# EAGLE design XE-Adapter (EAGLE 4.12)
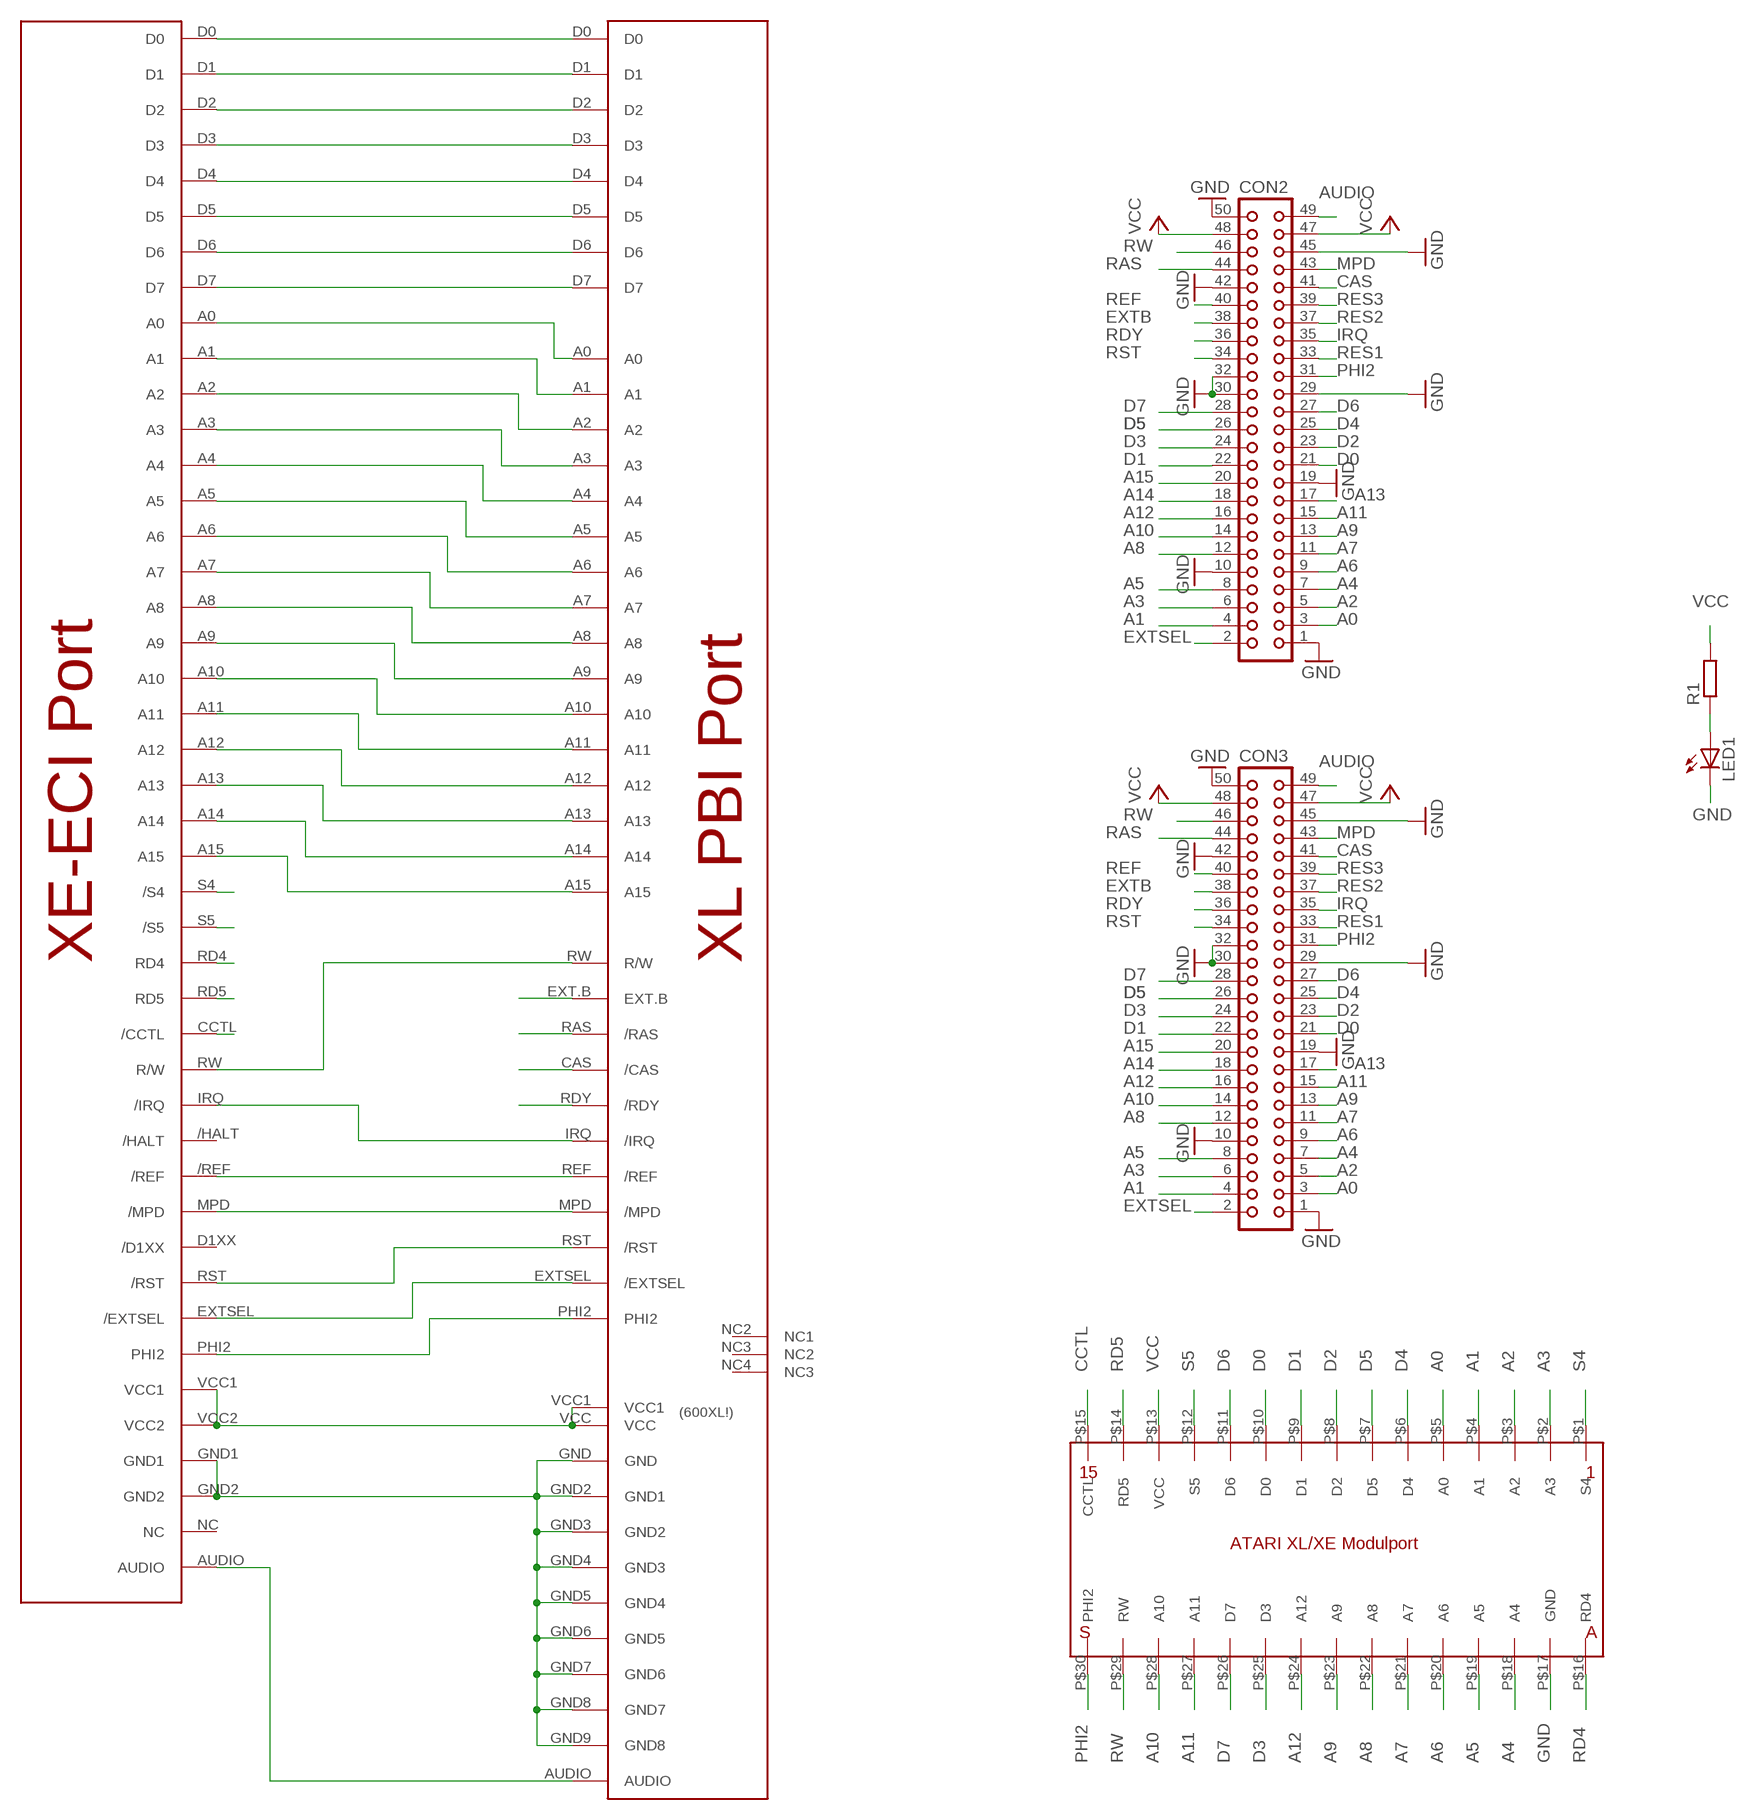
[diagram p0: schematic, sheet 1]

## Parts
CON2  CON50  [CON50]
CON3  CON50  [CON50]
LED1  LEDCHIPLED_1206  [CHIPLED_1206]
R1  R-EU_M0805  [M0805]
U$1  XE-ECI  [XE-ECI]
U$2  XL-PBI  [XL-PBI]
U$3  ATARI_MODULPORT  [MODUL_PORT]

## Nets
A0: CON2.3 CON3.3 U$1.A0 U$2.A0 U$3.P$5(A0)
A1: CON2.4 CON3.4 U$1.A1 U$2.A1 U$3.P$4(A1)
A2: CON2.5 CON3.5 U$1.A2 U$2.A2 U$3.P$3(A2)
A3: CON2.6 CON3.6 U$1.A3 U$2.A3 U$3.P$2(A3)
A4: CON2.7 CON3.7 U$1.A4 U$2.A4 U$3.P$18(A4)
A5: CON2.8 CON3.8 U$1.A5 U$2.A5 U$3.P$19(A5)
A6: CON2.9 CON3.9 U$1.A6 U$2.A6 U$3.P$20(A6)
A7: CON2.11 CON3.11 U$1.A7 U$2.A7 U$3.P$21(A7)
A8: CON2.12 CON3.12 U$1.A8 U$2.A8 U$3.P$22(A8)
A9: CON2.13 CON3.13 U$1.A9 U$2.A9 U$3.P$23(A9)
A10: CON2.14 CON3.14 U$1.A10 U$2.A10 U$3.P$28(A10)
A11: CON2.15 CON3.15 U$1.A11 U$2.A11 U$3.P$27(A11)
A12: CON2.16 CON3.16 U$1.A12 U$2.A12 U$3.P$24(A12)
A13: CON2.17 CON3.17 U$1.A13 U$2.A13
A14: CON2.18 CON3.18 U$1.A14 U$2.A14
A15: CON2.20 CON3.20 U$1.A15 U$2.A15
AUDIO: CON2.49 CON3.49 U$1.AUDIO U$2.AUDIO
CAS: CON2.41 CON3.41 U$2.CAS(/CAS)
CCTL: U$1.CCTL(/CCTL) U$3.P$15(CCTL)
D0: CON2.21 CON3.21 U$1.D0 U$2.D0 U$3.P$10(D0)
D1: CON2.22 CON3.22 U$1.D1 U$2.D1 U$3.P$9(D1)
D2: CON2.23 CON3.23 U$1.D2 U$2.D2 U$3.P$8(D2)
D3: CON2.24 CON3.24 U$1.D3 U$2.D3 U$3.P$25(D3)
D4: CON2.25 CON3.25 U$1.D4 U$2.D4 U$3.P$6(D4)
D5: CON2.26 CON3.26 U$1.D5 U$2.D5 U$3.P$7(D5)
D6: CON2.27 CON3.27 U$1.D6 U$2.D6 U$3.P$11(D6)
D7: CON2.28 CON3.28 U$1.D7 U$2.D7 U$3.P$26(D7)
EXTB: CON2.38 CON3.38 U$2.EXT.B
EXTSEL: CON2.2 CON3.2 U$1.EXTSEL(/EXTSEL) U$2.EXTSEL(/EXTSEL)
GND: CON2.1 CON2.10 CON2.19 CON2.29 CON2.30 CON2.32 CON2.42 CON2.45 CON2.50 CON3.1 CON3.10 CON3.19 CON3.29 CON3.30 CON3.32 CON3.42 CON3.45 CON3.50 LED1.C U$1.GND1 U$1.GND2 U$2.GND U$2.GND2(GND1) U$2.GND3(GND2) U$2.GND4(GND3) U$2.GND5(GND4) U$2.GND6(GND5) U$2.GND7(GND6) U$2.GND8(GND7) U$2.GND9(GND8) U$3.P$17(GND)
IRQ: CON2.35 CON3.35 U$1.IRQ(/IRQ) U$2.IRQ(/IRQ)
MPD: CON2.43 CON3.43 U$1.MPD(/MPD) U$2.MPD(/MPD)
N$4: LED1.A R1.1
PHI2: CON2.31 CON3.31 U$1.PHI2 U$2.PHI2 U$3.P$30(PHI2)
RAS: CON2.44 CON3.44 U$2.RAS(/RAS)
RD4: U$1.RD4 U$3.P$16(RD4)
RD5: U$1.RD5 U$3.P$14(RD5)
RDY: CON2.36 CON3.36 U$2.RDY(/RDY)
REF: CON2.40 CON3.40 U$1./REF U$2.REF(/REF)
RES1: CON2.33 CON3.33
RES2: CON2.37 CON3.37
RES3: CON2.39 CON3.39
RST: CON2.34 CON3.34 U$1.RST(/RST) U$2.RST(/RST)
RW: CON2.46 CON3.46 U$1.RW(R/W) U$2.RW(R/W) U$3.P$29(RW)
S4: U$1.S4(/S4) U$3.P$1(S4)
S5: U$1.S5(/S5) U$3.P$12(S5)
VCC: CON2.47 CON2.48 CON3.47 CON3.48 R1.2 U$1.VCC1 U$1.VCC2 U$2.VCC U$2.VCC1 U$3.P$13(VCC)
Unconnected: U$1./HALT U$1.D1XX(/D1XX) U$1.NC U$2.NC2(NC1) U$2.NC3(NC2) U$2.NC4(NC3)

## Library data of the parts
CON2 CON3 = con-harting:CON50: CONNECTOR
LED1 = led:LED: LED
R1 = rcl:R-EU_: RESISTOR, European symbol
U$1 = wf-atari:XE-ECI
U$2 = wf-atari:XL-PBI
U$3 = wf-atari:ATARI_MODULPORT

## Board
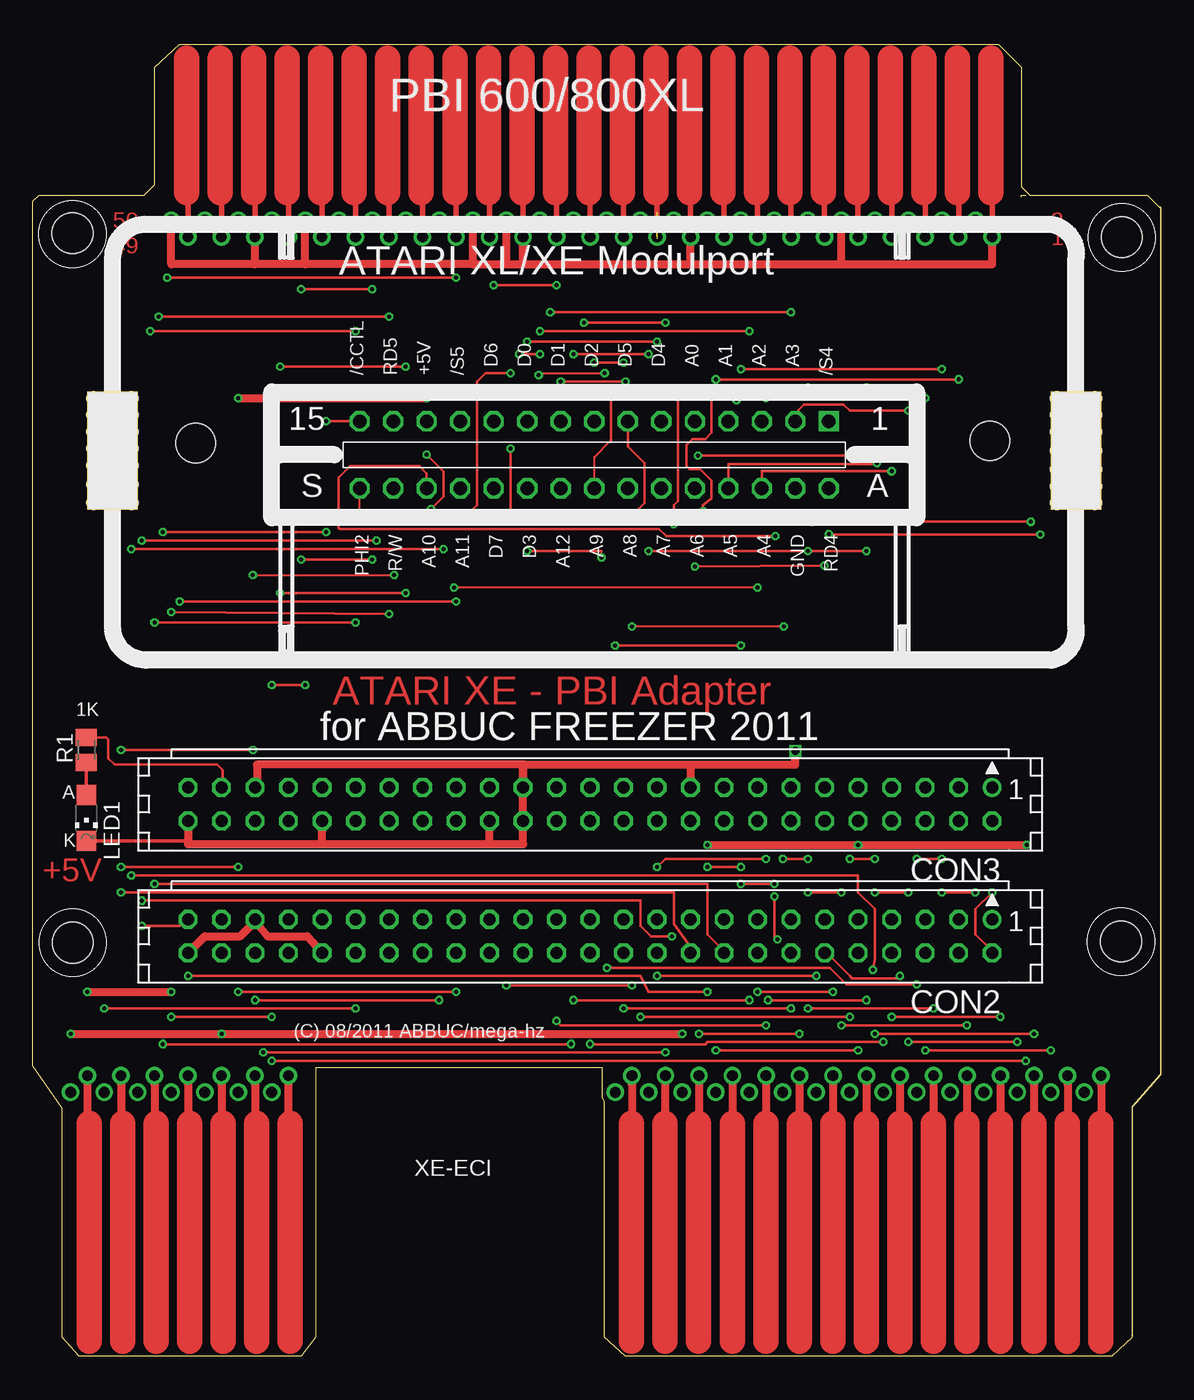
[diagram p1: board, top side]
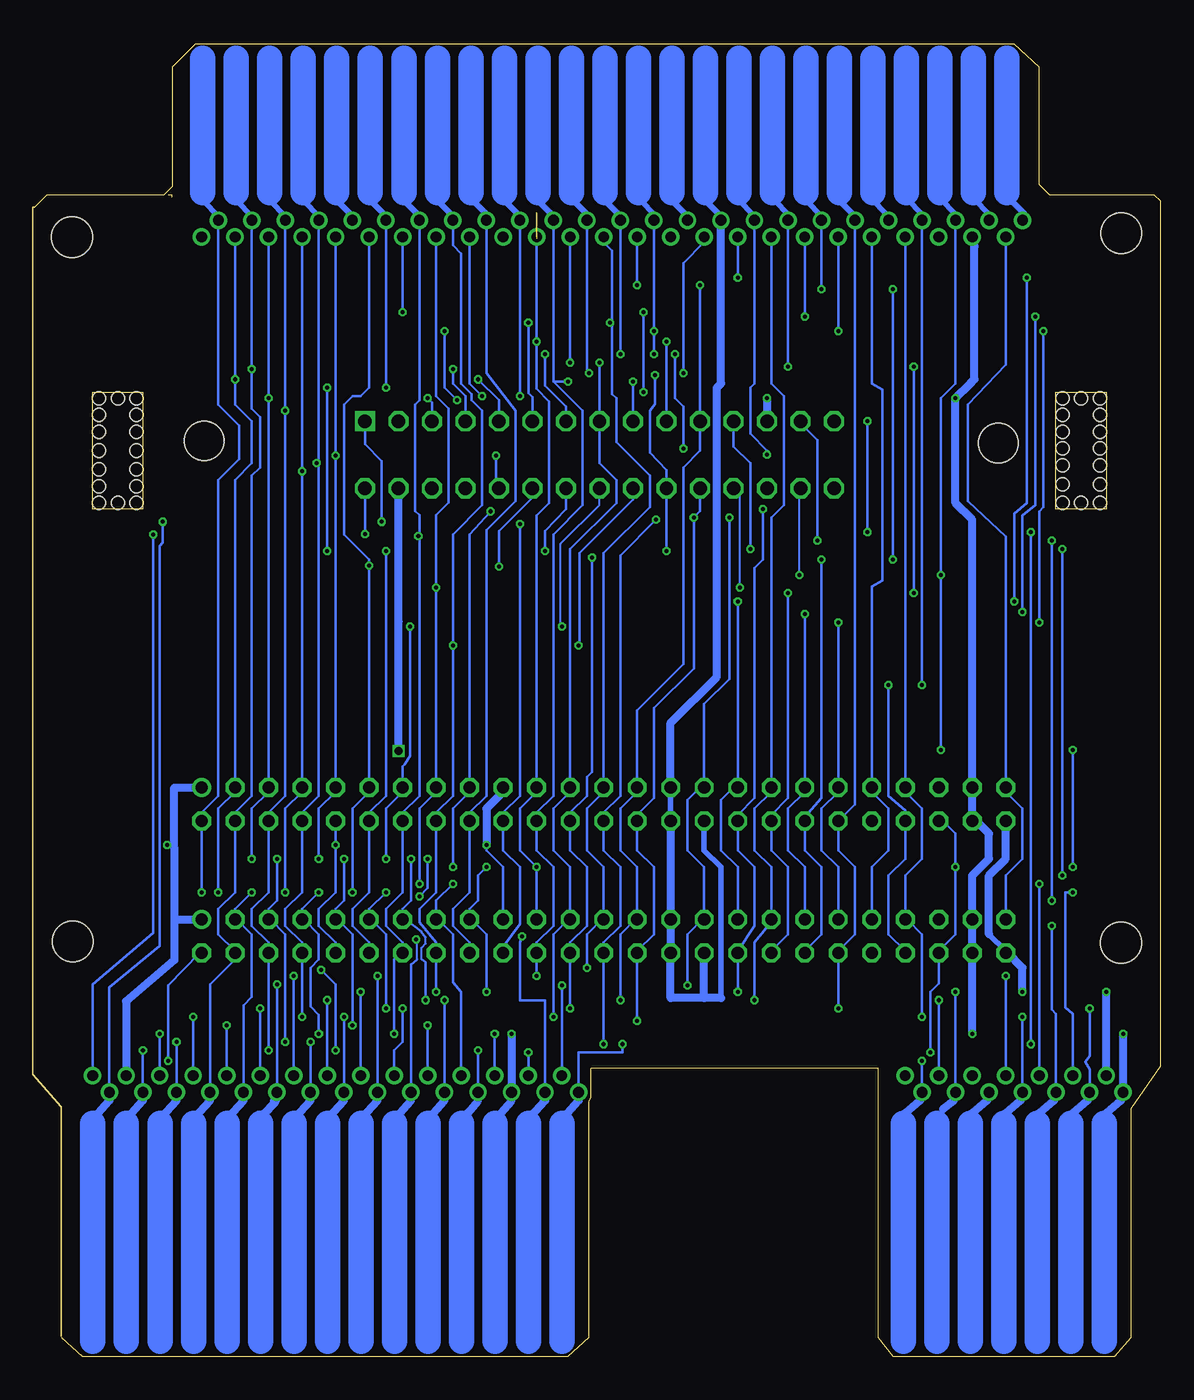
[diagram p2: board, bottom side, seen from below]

Size 85.49 x 99.44 mm. Coordinates in mm from the lower left corner, seen from the top.
Outline: 85.41,87.06 84.45,88.01 75.56,88.01 74.93,88.64 74.93,97.69 73.18,99.44 12.22,99.44 12.06,99.44 11.11,99.44 9.21,97.69 9.21,88.8 8.41,88.01 0.48,88.01 0,87.53 0,22 2.22,18.78 2.22,1.43 3.49,0 20.32,0 21.43,1.43 21.43,21.84 43.18,21.84
Outline: 83.34,1.43 81.76,0 44.93,0 43.34,1.43 43.34,19.29 43.18,19.61 43.18,21.83
Outline: 83.34,1.51 83.34,18.89 85.49,21.35 85.49,87.07 85.41,87.07
Copper layers (1*16): Top 0.035mm / dielectric 1.5mm / Bottom 0.035mm
Design rules "ITead_rule": minimum track width 6mil, minimum drill 12mil, track to track 6mil, track to pad 6mil, pad to pad 6mil, via to via 6mil, smd to smd 0mil, copper to edge 10mil, drill to drill 10mil, minimum pad ring 10mil, minimum via ring 6mil, stop-mask expansion 2mil, vias tented up to drill 100mil, thermal gap 10mil
Holes 1 mm at 4.6,72.61 6.03,72.61 7.46,72.61 4.6,71.34 4.6,70.07 4.6,68.8 4.6,67.53 4.6,66.1 4.6,64.67 7.46,64.67 6.03,64.67 7.46,66.1 7.46,67.53 7.46,68.8 7.46,71.34 7.46,70.07 77.63,72.61 80.49,72.61 77.63,64.67 80.49,64.67 79.06,64.67 79.06,72.61 77.63,71.34 77.63,70.07 77.63,65.94 77.63,67.21 77.63,68.64 80.49,68.64 80.49,70.07 80.49,71.34 80.49,67.21 80.49,65.94
Holes 3.1 mm at 2.98,85.13 82.53,84.81 3.02,31.35 82.47,31.43

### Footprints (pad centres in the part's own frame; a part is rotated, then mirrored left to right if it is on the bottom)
CON50 = drill 0.914 round: 1 -30.48,-1.27 | drill 0.914 octagon: 2 -30.48,1.27; 3 -27.94,-1.27; 4 -27.94,1.27; 5 -25.4,-1.27; 6 -25.4,1.27; 7 -22.86,-1.27; 8 -22.86,1.27; 9 -20.32,-1.27; 10 -20.32,1.27; 11 -17.78,-1.27; 12 -17.78,1.27; 13 -15.24,-1.27; 14 -15.24,1.27; 15 -12.7,-1.27; 16 -12.7,1.27; 17 -10.16,-1.27; 18 -10.16,1.27; 19 -7.62,-1.27; 20 -7.62,1.27; 21 -5.08,-1.27; 22 -5.08,1.27; 23 -2.54,-1.27; 24 -2.54,1.27; 25 0,-1.27; 26 0,1.27; 27 2.54,-1.27; 28 2.54,1.27; 29 5.08,-1.27; 30 5.08,1.27; 31 7.62,-1.27; 32 7.62,1.27; 33 10.16,-1.27; 34 10.16,1.27; 35 12.7,-1.27; 36 12.7,1.27; 37 15.24,-1.27; 38 15.24,1.27; 39 17.78,-1.27; 40 17.78,1.27; 41 20.32,-1.27; 42 20.32,1.27; 43 22.86,-1.27; 44 22.86,1.27; 45 25.4,-1.27; 46 25.4,1.27; 47 27.94,-1.27; 48 27.94,1.27; 49 30.48,-1.27; 50 30.48,1.27
CHIPLED_1206 = smd 1.5 x 1.5: A 0,-1.75; C 0,1.75
M0805 = smd 1.3 x 1.6: 1 -0.95,0; 2 0.95,0
XE-ECI = drill 0.813 round: /HALT -17.78,8.89; /REF -26.67,7.62; A0 37.465,7.62; A1 40.005,7.62; A2 42.545,7.62; A3 45.085,7.62; A4 43.815,8.89; A5 41.275,8.89; A6 38.735,8.89; A7 36.195,8.89; A8 33.655,8.89; A9 31.115,8.89; A10 18.415,8.89; A11 20.955,8.89; A12 28.575,8.89; A13 -20.32,8.89; A14 -22.86,8.89; A15 -25.4,8.89; AUDIO -24.13,7.62; CCTL 12.065,7.62; D0 24.765,7.62; D1 27.305,7.62; D1XX -19.05,7.62; D2 29.845,7.62; D3 26.035,8.89; D4 34.925,7.62; D5 32.385,7.62; D6 22.225,7.62; D7 23.495,8.89; EXTSEL -13.97,7.62; GND1 -27.94,8.89; GND2 46.355,8.89; IRQ -15.24,8.89; MPD -21.59,7.62; NC -12.7,8.89; PHI2 13.335,8.89; RD4 48.895,8.89; RD5 14.605,7.62; RST -16.51,7.62; RW 15.875,8.89; S4 47.625,7.62; S5 19.685,7.62; VCC1 -29.21,7.62; VCC2 17.145,7.62
XL-PBI = drill 0.813 round: A0 31.115,-8.255; A1 29.845,-6.985; A2 28.575,-8.255; A3 27.305,-6.985; A4 26.035,-8.255; A5 24.765,-6.985; A6 23.495,-8.255; A7 20.955,-8.255; A8 19.685,-6.985; A9 18.415,-8.255; A10 17.145,-6.985; A11 15.875,-8.255; A12 14.605,-6.985; A13 13.335,-8.255; A14 12.065,-6.985; A15 9.525,-6.985; AUDIO -27.305,-8.255; CAS -17.145,-8.255; D0 8.255,-8.255; D1 6.985,-6.985; D2 5.715,-8.255; D3 4.445,-6.985; D4 3.175,-8.255; D5 1.905,-6.985; D6 0.635,-8.255; D7 -0.635,-6.985; EXT.B -13.335,-6.985; EXTSEL 32.385,-6.985; GND -28.575,-6.985; GND2 -18.415,-6.985; GND3 -5.715,-6.985; GND4 -3.175,-6.985; GND5 22.225,-6.985; GND6 33.655,-8.255; GND7 10.795,-8.255; GND8 -1.905,-8.255; GND9 -22.225,-8.255; IRQ -9.525,-8.255; MPD -19.685,-8.255; NC2 -6.985,-8.255; NC3 -12.065,-8.255; NC4 -14.605,-8.255; PHI2 -4.445,-8.255; RAS -20.955,-6.985; RDY -10.795,-6.985; REF -15.875,-6.985; RST -8.255,-6.985; RW -23.495,-6.985; VCC -24.765,-8.255; VCC1 -26.035,-6.985
MODUL_PORT = drill 1.016 square: P$1 18.098,1.587 | drill 1.016 octagon: P$2 15.557,1.587; P$3 13.018,1.587; P$4 10.477,1.587; P$5 7.938,1.587; P$6 5.397,1.587; P$7 2.857,1.587; P$8 0.318,1.587; P$9 -2.223,1.587; P$10 -4.763,1.587; P$11 -7.303,1.587; P$12 -9.842,1.587; P$13 -12.383,1.587; P$14 -14.922,1.587; P$15 -17.462,1.587; P$16 18.098,-3.493; P$17 15.557,-3.493; P$18 13.018,-3.493; P$19 10.477,-3.493; P$20 7.938,-3.493; P$21 5.397,-3.493; P$22 2.857,-3.493; P$23 0.318,-3.493; P$24 -2.223,-3.493; P$25 -4.763,-3.493; P$26 -7.303,-3.493; P$27 -9.842,-3.493; P$28 -12.383,-3.493; P$29 -14.922,-3.493; P$30 -17.462,-3.493 | hole 3: 30.294,0.102; -29.9,-0.057

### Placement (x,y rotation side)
CON2  42.23,31.83 180 top
CON3  42.23,41.83 180 top
LED1  4.05,40.8 180 top
R1  4.05,45.96 90 top
U$1  32.07,12.38 0 top
U$2  39.05,93.09 0 top
U$3  42.23,69.28 0 top

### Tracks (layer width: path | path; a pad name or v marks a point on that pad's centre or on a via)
A0  (via drill 0.3)
  Top 0.203: v68.9,35.16 v71.44,35.16 | v70.17,74.04 v51.75,74.04
  Bottom 0.203: U$1.A0 69.53,26.59 68.9,27.23 68.9,31.99 70.17,33.26 | 70.17,33.26 CON2.3 | 70.17,33.26 70.17,33.89 v68.9,35.16 | v71.44,35.16 71.44,41.51 70.17,42.78 CON3.3 70.17,66.42 68.9,67.69 68.9,70.86 70.17,72.14 v70.17,74.04 | v70.17,74.04 70.17,73.72 | U$3.P$5 50.16,72.45 v51.75,74.04 | v70.17,74.04 | 70.12,84.81 70.17,84.85 U$2.A0 v70.17,74.04
A1  (via drill 0.3)
  Top 0.203: v68.9,74.83 v53.66,74.83
  Bottom 0.203: U$1.A1 72.07,28.18 70.17,30.08 CON2.4 70.17,30.72 71.44,31.99 71.44,33.89 70.17,35.16 CON3.4 70.17,41.2 68.9,42.47 68.9,66.74 68.26,67.37 68.26,71.18 68.9,71.82 v68.9,74.83 68.9,85.49 | U$3.P$4 52.7,72.77 53.66,73.72 v53.66,74.83 | 68.9,86.12 U$2.A1 68.9,85.49 | 68.9,85.49 68.9,85.41
A2  (via drill 0.3)
  Top 0.203: v66.36,23.81 v74.61,23.81 | v66.99,37.7 v68.9,37.7 | v67.63,72.61 v55.56,72.61
  Bottom 0.203: v66.36,23.81 66.36,31.99 67.47,33.1 CON2.5 67.63,33.89 66.99,34.53 v66.99,37.7 | v74.61,23.81 U$1.A2 | v68.9,37.7 68.9,41.51 67.63,42.78 CON3.5 v67.63,72.61 67.63,84.93 | U$3.P$3 55.24,72.29 v55.56,72.61 | 67.63,84.93 67.62,85.17 | 67.63,84.93 U$2.A2
A3  (via drill 0.3)
  Top 0.203: v67.63,23.18 v77.15,23.18 | v66.36,71.66 61.91,71.66 61.44,72.14 58.42,72.14 57.78,71.5 U$3.P$2
  Bottom 0.203: v77.15,23.18 U$1.A3 | v67.63,23.18 CON2.6 67.63,31.35 68.9,32.62 68.9,33.89 67.63,35.16 CON3.6 67.63,41.2 66.36,42.47 66.36,72.14 | 66.36,72.14 v66.36,71.66 | 66.36,85.49 66.36,85.41 | 66.36,85.49 U$2.A3 | 66.36,72.14 66.36,85.49
A4  (via drill 0.3)
  Top 0.203: v63.82,24.45 v75.88,24.45 | v63.82,35.16 v66.36,35.16 | U$3.P$18 55.24,67.07 v65.09,67.07
  Bottom 0.203: v75.88,24.45 U$1.A4 | v63.82,35.16 65.09,33.89 CON2.7 64.93,33.1 63.82,31.99 63.82,30.08 64.45,29.45 64.45,26.51 63.82,25.88 v63.82,24.45 | v66.36,35.16 66.36,41.51 65.09,42.78 CON3.7 65.4,43.42 65.09,43.73 v65.09,67.07 65.09,84.77 | 65.09,84.77 65.09,84.69 65.04,84.65 | 65.09,84.77 U$2.A4
A5  (via drill 0.3)
  Top 0.203: v65.09,25.72 v73.34,25.72 | U$3.P$19 52.7,67.63 64.06,67.63 v63.98,67.71
  Bottom 0.203: v73.34,25.72 U$1.A5 | v65.09,25.72 CON2.8 65.09,31.35 66.36,32.62 66.36,33.89 65.09,35.16 CON3.8 | CON3.8 65.09,40.88 | CON3.8 65.09,41.2 63.82,42.47 63.82,67.63 | 63.82,86.12 U$2.A5 63.82,85.57 | 63.82,85.57 63.82,85.41 | v63.98,67.71 63.9,67.71 63.82,67.63 | 63.82,67.63 63.82,85.57
A6  (via drill 0.3)
  Top 0.203: v61.28,25.08 v70.8,25.08 | v61.91,37.7 v63.82,37.7 | v62.55,68.26 v50.4,68.26
  Bottom 0.203: v70.8,25.08 U$1.A6 | v61.28,25.08 61.28,31.99 62.39,33.1 CON2.9 62.55,33.89 61.91,34.53 v61.91,37.7 | v63.82,37.7 63.82,41.51 62.55,42.78 CON3.9 v62.55,68.26 62.55,74.53 | 62.55,74.53 62.55,74.67 | U$3.P$20 50.16,65.88 50.4,66.12 v50.4,68.26 | 62.55,74.53 U$2.A6
A7  (via drill 0.3)
  Top 0.203: v58.74,26.35 v68.26,26.35 | v58.74,35.16 v61.28,35.16 | v60.01,59.93 v50.16,59.85
  Bottom 0.203: v68.26,26.35 U$1.A7 | v58.74,26.35 58.74,31.99 59.85,33.1 CON2.11 60.01,33.89 v58.74,35.16 | v61.28,35.16 61.28,41.51 60.01,42.78 CON3.11 60.01,59.85 | 60.01,59.85 60.01,60.39 61.91,62.29 61.91,72.14 61.28,72.77 60.64,72.77 60.01,73.41 60.01,84.69 | 60.01,84.69 59.96,84.65 | U$3.P$21 47.62,65.09 50.16,62.55 v50.16,59.85 | 60.01,59.85 v60.01,59.93 | 60.01,84.69 U$2.A7
A8  (via drill 0.3)
  Top 0.203: 61.91,28.81 | 61.91,28.81 62.07,28.65 65.56,28.65 v65.72,28.81 | v63.18,61.02 v58.74,61.02 58.74,60.96 58.66,61.04 v46.67,61.04 | v63.18,73.41 v58.74,73.41 | 61.91,28.81 60.17,30.56 CON2.12
  Bottom 0.203: U$1.A8 v65.72,28.81 | v58.74,61.02 58.74,42.47 60.01,41.2 CON3.12 60.01,35.16 61.28,33.89 61.28,32.62 60.01,31.35 CON2.12 | v63.18,61.02 v63.18,73.41 | 58.74,86.28 U$2.A8 58.74,85.57 | 58.74,85.57 58.74,85.41 | U$3.P$22 45.08,64.21 46.67,62.55 v46.67,61.04 | v58.74,73.41 58.74,85.57
A9  (via drill 0.3)
  Top 0.152: U$3.P$23 42.54,65.8 42.62,65.88 42.54,65.96 42.54,68.17 | v56.91,55.31 56.97,55.31 56.99,55.32 v45.4,55.32
  Top 0.203: v55.72,26.99 v63.18,26.99 | v56.83,37.7 v58.74,37.7 | 42.54,68.17 43.81,69.44 43.81,73.09 v39.21,73.09 | v39.21,79.12 v57.47,79.12
  Bottom 0.152: 55.72,29.84 56.04,30.08 56.04,30.96 55.72,31.27 55.72,31.75 56.04,32.15 57.47,33.26 57.31,33.18 57.39,33.1 CON2.13 | U$3.P$23 42.54,64.53 45.48,61.59 45.48,55.4 v45.4,55.32
  Bottom 0.203: 57.31,33.1 CON2.13 57.47,33.89 56.83,34.53 v56.83,37.7 | v63.18,26.99 U$1.A9 | v58.74,37.7 58.74,41.51 57.47,42.78 CON3.13 57.47,44.69 57.31,44.85 | v55.72,26.99 55.72,29.45 55.72,29.84 | v57.47,79.12 57.63,79.28 | v56.91,55.31 56.91,45.48 57.31,44.85 | 57.31,44.85 | v39.21,73.09 v39.21,79.12 | v57.47,79.12 | 57.47,85.01 U$2.A9 57.47,79.14 | 57.47,79.14 | v57.47,79.12 57.47,79.14
A10  (via drill 0.3)
  Top 0.203: v50.48,24.45 v58.1,24.45 | U$3.P$28 29.84,66.91 29.29,67.47 24.05,67.47 23.18,66.59 23.18,62.79 23.26,62.71 47.47,62.71 48.02,62.15 v56.28,62.15
  Bottom 0.203: U$1.A10 v50.48,24.45 | 57.47,30.72 CON2.14 | v58.1,24.45 58.1,30.08 57.47,30.72 | 57.47,30.72 57.47,31.35 58.74,32.62 58.74,33.89 57.47,35.16 CON3.14 57.47,41.2 56.2,42.47 56.2,62.15 | 56.2,85.64 56.2,85.41 | 56.2,85.64 U$2.A10 | 56.2,62.15 56.2,63.74 56.51,64.06 56.51,72.14 56.2,72.45 56.2,85.64 | 56.2,62.15 v56.28,62.15
A11  (via drill 0.3)
  Top 0.152: v54.93,58.26 v31.91,58.26
  Top 0.203: v53.66,35.8 v56.2,35.8
  Bottom 0.152: U$3.P$27 31.91,65.78 v31.91,58.26
  Bottom 0.203: U$1.A11 53.02,27.62 53.66,28.34 53.66,31.99 54.93,33.26 | 54.93,33.26 CON2.15 | 54.93,33.26 54.93,34.53 v53.66,35.8 | v56.2,35.8 56.2,41.51 54.93,42.78 CON3.15 v54.93,58.26 54.93,63.74 53.97,64.69 53.97,69.29 | 53.97,69.29 53.97,69.28 | 53.97,69.29 53.97,71.82 54.93,72.77 54.93,84.69 55.01,84.77 54.94,84.83 U$2.A11 54.93,85.01 54.88,84.97
A12  (via drill 0.3)
  Top 0.203: v54.93,27.62 v60.64,27.62 | v53.66,53.88 v44.13,53.88
  Bottom 0.203: v54.93,27.62 CON2.16 54.93,31.35 56.2,32.86 56.2,33.89 54.93,35.16 CON3.16 54.93,41.2 53.66,42.47 v53.66,53.88 53.66,62.29 51.43,64.52 51.43,71.66 52.23,72.45 52.23,72.93 53.02,73.72 53.02,83.58 53.66,84.22 U$2.A12 | v60.64,27.62 U$1.A12 | U$3.P$24 40,64.93 44.05,60.88 44.05,53.82 44.13,53.82 44.21,53.9 v44.13,53.88
A13  (via drill 0.3)
  Top 0.203: v51.12,27.62 46.67,27.62 46.04,28.81 v11.75,28.81 | v51.12,37.07 v53.66,37.07 | v50.8,64.04 50.8,64.52 51.43,64.99 51.43,66.36 50.56,67.23 49.77,67.23 49.53,67.47 49.53,69.06 50.01,69.53 50.96,69.53 51.43,70.01 v51.43,72.77 51.43,72.79
  Bottom 0.203: U$1.A13 11.75,26.99 | 11.75,26.99 11.75,27.62 | v51.12,27.62 51.12,31.99 52.23,33.1 CON2.17 52.39,33.89 51.75,34.53 51.75,36.43 v51.12,37.07 | 11.75,26.99 v11.75,28.81 | v53.66,37.07 53.66,41.51 52.39,42.78 CON3.17 52.39,62.29 v50.8,64.04 | v51.43,72.77 52.39,73.72 52.39,84.93 | 52.39,84.93 52.31,85.09 | 52.39,84.93 U$2.A13
A14  (via drill 0.3)
  Top 0.203: CON2.18 52.39,30.72 51.12,31.99 51.12,35.8 v9.21,35.8
  Bottom 0.203: U$1.A14 v9.21,35.8 | CON2.18 52.39,31.35 53.66,32.62 53.66,33.89 52.39,35.16 CON3.18 | CON3.18 52.39,40.88 | CON3.18 52.39,41.2 51.12,42.47 51.12,62.61 48.89,64.83 48.89,71.66 51.12,74.52 51.12,85.64 | 51.12,85.64 51.12,85.41 | 51.12,85.64 U$2.A14
A15  (via drill 0.3)
  Top 0.203: CON2.20 49.85,31.04 48.58,32.78 48.58,35.16 v6.67,35.16 | v48.58,63.09 48.58,64.52 48.89,64.83 48.89,72.45 v48.58,72.77
  Bottom 0.178: 6.67,25.96 7.22,26.43 7.22,35.16
  Bottom 0.203: CON2.20 49.85,31.04 48.58,32.78 48.58,37.07 49.85,38.34 CON3.20 49.85,41.2 48.58,42.47 v48.58,63.09 | U$1.A15 6.67,25.96 | 7.22,35.16 v6.67,35.16 | 48.58,85.64 48.58,85.41 | 48.58,85.64 U$2.A15 | v48.58,72.77 48.58,85.64
AUDIO  (via drill 0.3)
  Top 0.203: CON2.49 11.75,33.26 11.11,32.62 v8.25,32.62
  Bottom 0.203: CON2.49 11.75,36.43 10.48,37.7 10.48,41.51 11.75,42.78 CON3.49 11.75,62.13 14.6,64.83 14.6,72.14 11.75,75.15 U$2.AUDIO 11.75,84.85 11.7,84.81 | U$1.AUDIO 7.94,25.96 8.25,26.27 v8.25,32.62
CAS
  Bottom 0.203: CON2.41 21.91,37.07 20.64,38.34 20.64,41.51 21.91,42.78 CON3.41 21.91,58.32 21.11,58.8 21.11,73.25 21.91,73.72 21.91,85.01 | 21.91,85.01 21.98,85.01 | 21.91,85.01 U$2.CAS | 21.99,84.77 21.99,85.01 21.91,85.01
CCTL  (via drill 0.3)
  Top 0.203: v9.84,23.65 v40.8,23.65 | v9.84,62.45 v22.22,62.45 | v22.22,70.86 U$3.P$15
  Bottom 0.203: U$1.CCTL 44.13,23.02 40.8,23.02 v40.8,23.65 | v9.84,23.65 v9.84,62.45 | v22.22,62.45 v22.22,70.86
D0  (via drill 0.3)  (3 unrouted)
  Top 0.203: v47.31,37.07 47.94,37.7 v55.56,37.7 | 56.36,31.43 v56.44,31.59 56.44,31.67 56.2,31.67 v56.2,34.84 | v47.31,76.9 v37.46,76.9
  Bottom 0.152: 56.83,29.69 56.36,30.08 56.36,31.51 v56.44,31.59 | v56.44,31.59
  Bottom 0.203: CON2.21 v47.31,37.07 48.58,38.34 48.58,41.51 47.31,42.78 CON3.21 47.31,63.72 46.35,64.67 46.35,72.37 47.31,73.33 47.31,74.2 47.31,74.36 | v55.56,37.7 55.56,35.48 v56.2,34.84 | U$1.D0 56.83,29.69 | 47.31,74.36 v47.31,76.9 47.31,84.85 47.31,85.01 | 47.31,74.36 | v37.46,76.9 U$3.P$10 | 47.26,84.81 47.39,84.85 U$2.D0 47.32,84.83 47.39,84.77 47.31,84.69
D1  (via drill 0.3)
  Top 0.203: v47.31,28.81 47.31,28.97 47.47,28.81 v59.37,28.81 | v44.93,73.88 v40,73.88
  Bottom 0.203: v59.37,28.81 U$1.D1 | v47.31,28.81 CON2.22 47.31,31.35 46.04,32.62 46.04,37.07 47.31,38.34 CON3.22 47.31,41.2 46.04,42.47 46.04,62.29 43.81,64.52 43.81,71.66 46.04,73.88 | v40,73.88 U$3.P$9 | 46.04,73.88 v44.93,73.88 | 46.04,85.49 46.04,85.41 | 46.04,85.49 U$2.D1 | 46.04,73.88 46.04,85.49
D2  (via drill 0.3)
  Top 0.203: v46.04,25.72 v61.91,25.72 | v42.54,75.31 v44.77,75.31
  Bottom 0.203: v61.91,25.72 U$1.D2 | 44.77,33.26 CON2.23 | v46.04,25.72 46.04,31.99 44.77,33.26 | 44.77,33.26 44.77,37.07 46.04,38.34 46.04,41.51 44.77,42.78 CON3.23 44.77,61.18 41.27,64.67 41.27,66.42 42.54,67.69 42.54,71.02 | 42.54,71.02 v42.54,75.31 | 42.54,71.02 U$3.P$8 | v42.54,75.31 | 44.77,85.01 44.69,84.85 | 44.77,85.01 U$2.D2 | v44.77,75.31 44.77,85.01
D3  (via drill 0.3)
  Top 0.152: 43.1,61.04 43.08,61.02 v43.1,60.55 | v43.34,74.52 38.35,74.52 v38.34,74.37
  Top 0.203: v44.77,26.35 v57.47,26.35 | 43.1,61.04 v37.46,61.04
  Bottom 0.152: U$3.P$25 37.46,65.8 37.39,65.88 37.46,65.96
  Bottom 0.203: v44.77,26.35 CON2.24 44.77,31.35 43.5,32.62 43.5,37.07 44.77,38.34 CON3.24 44.77,41.2 43.5,42.47 43.5,43.89 43.1,44.29 v43.1,60.55 | v57.47,26.35 57.47,23.81 58.1,23.18 U$1.D3 | v43.34,74.52 43.5,74.36 | 43.5,74.36 43.5,74.52 | 43.5,85.57 43.5,85.41 | 43.5,85.57 U$2.D3 | v37.46,61.04 U$3.P$25 | v38.34,74.37 38.34,72.15 38.73,71.67 38.73,68.5 37.46,67.15 37.46,65.96 | 43.5,74.36 43.5,85.57
D4  (via drill 0.3)
  Top 0.203: v66.99,28.18 61.67,28.18 60.4,29.45 v43.5,29.45 | v41.75,78.33 v47.94,78.33
  Bottom 0.203: v66.99,28.18 U$1.D4 | CON2.25 42.23,33.26 | v43.5,29.45 43.5,31.99 42.23,33.26 | 42.23,33.26 42.23,37.07 43.5,38.34 43.5,41.51 42.23,42.78 CON3.25 42.23,60.86 38.73,64.36 38.73,66.74 41.27,69.28 41.27,72.61 41.59,72.93 41.59,78.33 | 42.23,84.44 41.59,83.8 41.59,78.33 | U$3.P$6 47.62,72.69 47.94,73.01 v47.94,78.33 | 41.59,78.33 v41.75,78.33 | U$2.D4 42.24,84.83 42.39,84.69 42.18,84.49 | U$2.D4 42.23,84.85 | 42.23,84.44 42.15,84.77 | 42.23,84.44 U$2.D4
D5  (via drill 0.3)
  Top 0.203: v38.26,63.4 45.08,63.4 46.35,64.67 46.35,67.69 45.08,68.96 45.08,70.71 44.93,70.86 U$3.P$7 | v46.67,75.95 v40.96,75.95 | v42.23,23.65 50.96,23.65 51.12,23.81 v64.45,23.81
  Bottom 0.203: v64.45,23.81 U$1.D5 | v42.23,23.65 CON2.26 42.23,31.35 40.96,32.62 40.96,37.07 42.23,38.34 CON3.26 42.23,41.2 40.96,42.47 40.96,60.7 v38.26,63.4 | v46.67,75.95 46.67,73.56 45.08,71.98 45.08,71.02 44.93,70.86 U$3.P$7 | 40.96,85.57 40.96,85.41 | 40.96,85.57 U$2.D5 | v40.96,75.95 40.96,85.57
D6  (via drill 0.3)
  Top 0.203: v40.96,26.99 v54.29,26.99 | v34.92,81.18 v39.69,81.18
  Bottom 0.203: v54.29,26.99 U$1.D6 | 39.69,33.26 CON2.27 | v40.96,26.99 40.96,31.99 39.69,33.26 | 39.69,33.26 39.69,37.07 40.96,38.34 40.96,41.51 39.69,42.78 CON3.27 39.69,48.96 36.19,52.45 36.19,67.37 34.92,68.64 U$3.P$11 v34.92,81.18 | 39.69,84.93 39.68,85.01 | 39.69,84.93 U$2.D6 | v39.69,81.18 39.69,84.93 | 39.69,84.93 39.61,84.85
D7  (via drill 0.3)
  Top 0.203: v35.4,63.56 35.56,63.56 36.19,64.2 v36.19,68.8 | v36.83,75.95 v38.42,75.95 | v38.42,77.69 v54.29,77.69 | v39.69,25.4 40,25.08 v55.56,25.08
  Bottom 0.203: v55.56,25.08 U$1.D7 | v39.69,25.4 CON2.28 39.69,30.72 38.42,31.99 38.42,37.07 39.69,38.34 CON3.28 39.69,41.04 38.42,42.31 38.42,49.12 35.4,52.13 v35.4,63.56 35.4,63.58 34.92,64.06 U$3.P$26 | v36.19,68.8 36.19,71.98 36.83,72.61 v36.83,75.95 | v38.42,75.95 | v38.42,75.95 v38.42,77.69 38.42,85.72 | v54.29,77.69 54.29,73.41 v53.34,72.45 | 38.42,85.72 38.42,85.57 | 38.42,85.72 U$2.D7
EXTB  (via drill 0.3)
  Top 0.203: v25.72,60.39 v20.32,60.39 | v20.32,80.87 v25.72,80.87
  Bottom 0.203: CON2.38 26.99,30.72 25.72,31.99 25.72,37.07 26.99,38.34 CON3.38 26.99,40.88 25.72,42.31 v25.72,60.39 | v20.32,60.39 v20.32,80.87 | v25.72,80.87 U$2.EXT.B
EXTSEL  (via drill 0.3)
  Top 0.203: v18.1,22.38 v75.25,22.38 | CON2.2 72.71,30.72 71.44,31.99 71.44,33.89 v72.71,35.16
  Bottom 0.203: U$1.EXTSEL v18.1,22.38 | CON2.2 72.87,30.56 75.25,28.1 v75.25,22.38 | CON3.2 72.71,40.88 | v72.71,35.16 CON3.2 | CON3.2 72.71,41.2 71.44,42.47 71.44,66.42 69.85,68.01 69.85,70.55 71.44,72.14 71.44,85.49 | 71.44,86.12 U$2.EXTSEL 71.44,85.49 | 71.44,85.49 71.44,85.41
GND  (via drill 0.3, 0.61)
  Top 0.254: 11.75,39.13 11.83,39.13 11.74,39.05 LED1.C
  Top 0.406: 16.83,32.94 CON2.45 | 16.99,43.1 CON3.45 | CON3.42 21.91,40.72
  Top 0.61: v4.13,27.62 v10.48,27.62 | CON2.50 13.02,31.83 15.72,31.83 16.83,32.94 17.78,31.83 20.8,31.83 CON2.42 | 21.91,38.81 CON3.42 | v75.33,38.73 v62.55,38.73 v51.12,38.73 | U$2.GND 10.48,82.77 16.83,82.77 | 33.34,82.77 20.64,82.77 | 20.64,82.77 16.83,82.77 | 33.34,82.77 35.88,82.77 | 35.88,82.77 37.15,82.77 | 37.15,82.77 49.85,82.77 | 61.28,82.77 72.71,82.77 72.71,82.79 | 72.71,82.79 U$2.GND6 | 61.28,82.77 U$2.GND5 | 49.85,82.77 U$2.GND7 | U$2.GND3 33.34,82.77 | 35.88,82.77 U$2.GND4 | 37.15,82.77 U$2.GND8 | 16.83,82.79 U$2.GND9 | 37.15,44.53 37.15,44.85 37.31,44.85 | 37.15,44.53 CON3.29 | 37.31,44.85 49.85,44.85 | 49.85,44.85 CON3.19 | 21.91,38.81 21.91,40.72 | 21.91,38.81 11.75,38.81 11.75,39.13 CON3.50 | 16.99,43.1 16.99,44.85 37.31,44.85 | 21.91,38.81 34.61,38.81 | 34.61,38.81 37.15,38.81 37.15,44.53 | 34.61,38.81 CON3.32 | 49.85,82.77 61.28,82.77 | 72.71,82.79 72.66,82.74 | 16.83,82.77 16.83,82.79 | 16.83,82.79 16.78,82.74 | 20.64,82.77 U$2.GND2 | 49.85,44.85 57.78,44.85 v57.78,45.88
  Bottom 0.203: 11.59,30.56 CON2.50 11.75,30.72 | CON2.32 34.61,30.72 | CON2.29 37.15,33.26 | CON3.30 37.15,40.88 | CON2.19 49.85,37.07 51.12,38.34 v51.12,38.73 | CON3.19 49.85,42.78 | CON2.10 62.55,31.35 63.82,32.62 63.82,33.89 62.55,35.16 v62.55,38.73 CON3.10 | 72.87,43.1 CON3.1 | v75.33,38.73 74.77,38.5
  Bottom 0.406: 11.75,30.72 13.02,31.99 | CON3.29 CON3.30 | 33.34,27.15 33.34,37.07 34.61,38.34 CON3.32
  Bottom 0.61: U$1.GND1 v4.13,27.62 | 11.59,30.56 10.48,29.45 v10.48,27.62 | CON3.50 11.75,37.7 13.02,36.43 13.02,31.99 | 34.61,27.15 37.15,27.15 CON2.30 CON2.29 CON3.30 | 34.61,27.15 CON2.32 | 33.34,27.15 34.61,27.15 | v51.12,38.73 51.12,41.51 49.85,42.78 | 72.87,43.1 74.77,43.1 74.77,38.5 74.77,35.48 74.77,33.1 | CON3.29 37.15,48.01 33.65,51.5 33.65,73.41 33.34,73.72 U$2.GND3 33.34,86.12 | U$1.GND2 78.42,26.91 74.77,30 74.77,33.1 | 74.77,33.1 CON2.1 | v57.78,45.88 57.78,55.72 57.78,55.64 U$3.P$17 57.78,65.88
IRQ  (via drill 0.3)
  Top 0.203: v16.83,26.99 v30.8,26.99
  Bottom 0.203: U$1.IRQ v16.83,26.99 | v30.8,26.99 30.8,31.35 29.37,33.1 CON2.35 29.53,37.07 30.8,38.34 30.8,41.51 29.53,42.78 CON3.35 29.53,63.56 28.57,64.52 28.57,72.77 29.53,73.72 U$2.IRQ 29.53,84.85 29.48,84.81
MPD  (via drill 0.3)
  Top 0.203: v10.48,25.72 v18.1,25.72
  Bottom 0.203: U$1.MPD v10.48,25.72 | v18.1,25.72 18.1,31.99 19.21,33.1 CON2.43 19.37,36.43 18.1,37.7 18.1,41.51 19.37,42.78 CON3.43 19.37,84.85 | 19.37,84.85 19.37,84.91 | 19.32,84.65 19.37,84.69 U$2.MPD 19.37,84.85
N$4
  Top 0.254: LED1.A 4.13,42.62 4.05,42.7 R1.1
PHI2  (via drill 0.3)
  Top 0.152: v32.7,63.56 24.76,63.56 U$3.P$30
  Top 0.203: v45.4,28.1 v35.88,28.1 | v32.7,63.56 33.65,64.52 33.65,73.88 34.29,74.52 v36.19,74.52
  Bottom 0.203: U$1.PHI2 v45.4,28.1 | 34.61,33.26 CON2.31 | v35.88,28.1 35.88,31.99 34.61,33.26 | 34.61,33.26 34.61,37.07 35.88,38.34 35.88,42.15 | CON3.31 34.61,43.42 35.88,42.15 | 35.88,42.15 34.77,43.26 34.77,43.42 34.61,43.58 34.61,49.43 32.7,51.34 v32.7,63.56 | 34.47,84.83 34.45,84.85 | 34.47,84.83 U$2.PHI2 34.62,84.83 34.69,84.77 34.61,84.69 34.61,84.45 36.19,82.87 v36.19,74.52 | 34.47,84.83 34.56,84.74
RAS  (via drill 0.3)
  Top 0.203: v20.64,50.86 v18.1,50.86
  Bottom 0.203: CON2.44 19.37,30.72 20.64,31.99 20.64,36.43 19.37,37.7 CON3.44 | CON3.44 19.37,40.88 | v20.64,50.86 20.64,42.47 19.37,41.35 CON3.44 | 18.1,85.72 18.1,85.41 | 18.1,85.72 U$2.RAS | v18.1,50.86 18.1,85.72
RD4  (via drill 0.3)
  Top 0.203: v76.36,62.29 60.34,62.29 v60.32,62.31
  Bottom 0.203: U$1.RD4 80.96,28.18 76.36,32.07 v76.36,62.29 | U$3.P$16 60.34,65.78 60.4,65.72 60.32,65.64 v60.32,62.31
RD5  (via drill 0.3)
  Top 0.203: v48.42,31.83 46.83,31.83 46.04,32.62 46.04,34.53 v8.25,34.53 | v8.25,61.82 v26.03,61.82
  Bottom 0.203: U$1.RD5 46.67,26.99 48.58,26.99 48.58,31.35 v48.42,31.83 | v8.25,34.53 v8.25,61.82 | U$3.P$14 27.46,70.86 26.03,69.44 v26.03,61.82
RDY  (via drill 0.3)
  Top 0.203: v18.73,74.99 v28.26,74.99 | v28.26,57.85 v18.73,57.85
  Bottom 0.203: CON2.36 29.53,30.72 28.26,31.99 28.26,37.07 29.53,38.34 CON3.36 29.53,41.04 28.26,42.31 v28.26,57.85 | v18.73,57.85 v18.73,74.99 | 28.26,85.49 28.26,85.41 | 28.26,85.49 U$2.RDY | v28.26,74.99 28.26,85.49
REF  (via drill 0.3)
  Top 0.203: v5.4,26.35 v24.45,26.35
  Bottom 0.203: v24.45,26.35 CON2.40 24.45,30.72 23.18,31.99 23.18,37.07 24.45,38.34 CON3.40 24.45,40.88 24.13,40.88 23.18,41.83 23.18,85.49 | U$1./REF 5.4,21.75 5.71,22.3 5.4,22.78 v5.4,26.35 | 23.18,85.49 23.18,85.41 | 23.18,85.49 U$2.REF
RES1  (via drill 0.3)
  Top 0.203: 10,81.74 10.16,81.58 v10.16,81.74 | v10.16,81.74 v32.07,81.74 | v32.07,81.74 | v32.07,57.21 v11.11,57.21 | v10.16,81.74
  Bottom 0.203: CON2.33 32.07,37.07 33.34,38.34 33.34,42.15 32.07,43.42 | 32.07,43.42 CON3.33 | 32.07,43.42 v32.07,57.21 | v11.11,57.21 11.11,63.88 10.16,64.67 v10.16,81.74 | 32.07,84.93 32.14,84.93 | 32.07,84.93 32.07,85.09 | v32.07,81.74 32.07,84.93
RES2  (via drill 0.3)
  Top 0.203: v9.52,78.8 v26.99,78.8 | v26.99,56.26 v10.48,56.42
  Bottom 0.203: CON2.37 26.99,37.07 28.26,38.34 28.26,41.51 26.99,42.78 CON3.37 v26.99,56.26 | v10.48,56.42 10.48,63.72 9.52,64.52 v9.52,78.8 | v26.99,78.8 26.99,85.01
RES3  (via drill 0.3)
  Top 0.203: v8.89,77.69 v24.45,77.69 | v24.45,55.62 v9.21,55.62 | v8.89,77.69
  Bottom 0.203: CON2.39 24.45,37.07 25.72,38.34 25.72,41.51 24.45,42.78 CON3.39 v24.45,55.62 | v9.21,55.62 9.21,64.04 8.89,64.36 v8.89,77.69 | 24.4,84.65 24.45,84.69 v24.45,77.69
RST  (via drill 0.3)
  Top 0.203: v15.56,27.62 v32.07,27.62 | v30.16,64.2 31.11,65.15 31.11,67.06 v29.84,68.33
  Bottom 0.203: U$1.RST v15.56,27.62 | v32.07,27.62 CON2.34 32.07,30.72 30.8,32.62 30.8,37.07 32.07,38.34 CON3.34 32.07,41.04 30.8,42.31 30.8,59.75 30.16,60.39 v30.16,64.2 | v29.84,68.33 29.84,68.64 31.11,69.91 31.11,73.41 30.8,73.72 30.8,85.49 | 30.8,85.49 30.8,85.41 | 30.8,85.49 U$2.RST
RW  (via drill 0.3)
  Top 0.152: v16.67,59.21 v27.38,59.21
  Top 0.203: v17.46,23.02 v47.94,23.02 | v6.67,45.96 v16.67,45.96 | v15.56,37.07 v6.67,37.07
  Bottom 0.152: U$3.P$29 27.38,65.78 v27.38,59.21 | v16.67,59.21
  Bottom 0.203: v47.94,23.02 U$1.RW | v17.46,23.02 17.46,27.62 16.83,28.26 CON2.46 16.83,30.72 15.56,31.99 v15.56,37.07 15.56,39.61 16.51,40.56 CON3.46 | v6.67,37.07 v6.67,45.96 | v16.67,45.96 v16.67,59.21 16.67,72.61 15.56,73.72 15.56,85.57 | 15.56,85.57 15.56,85.41 | 15.56,85.57 U$2.RW
S4  (via drill 0.3)
  Top 0.203: v75.64,63.25 v59.05,63.25
  Bottom 0.178: 75.64,62.85 75.64,61.66 75.88,61.42 75.88,31.12
  Bottom 0.203: U$3.P$1 60.32,69.12 59.05,67.85 v59.05,63.25 | U$1.S4 79.69,27.94 75.88,31.12 | 75.64,62.85 v75.64,63.25
S5  (via drill 0.3)
  Top 0.203: v62.55,23.18 v51.75,23.18 | v63.66,29.29 63.82,30.08 63.82,33.89 62.55,35.16 62.55,36.43 v7.46,36.43 | v7.46,61.18 v31.11,61.18
  Bottom 0.203: v51.75,23.18 U$1.S5 | v62.55,23.18 62.55,28.18 v63.66,29.29 | v7.46,36.43 v7.46,61.18 | v31.11,61.18 31.11,67.69 32.38,68.96 U$3.P$12
VCC  (via drill 0.3)
  Top 0.203: 14.37,43.1 14.37,44.45 13.97,44.85 6.19,44.85 5.71,45.32 5.71,46.75 5.56,46.91 4.13,46.91 4.12,46.91 R1.2
  Top 0.254: CON3.47 14.37,43.1
  Top 0.61: v49.21,24.45 v14.29,24.45 v2.86,24.45 | v15.56,72.61 v29.84,72.61 | U$2.VCC U$2.VCC1
  Bottom 0.203: 14.29,40.88 CON3.48 | U$3.P$13 29.84,70.71
  Bottom 0.61: v49.21,24.45 U$1.VCC2 | U$1.VCC1 v2.86,24.45 | v14.29,24.45 CON2.48 CON2.47 14.29,36.43 13.02,37.7 13.02,39.61 14.29,40.88 CON3.47 14.29,63.4 15.56,64.67 v15.56,72.61 14.44,73.73 | v29.84,72.61 U$3.P$13 | 14.44,73.73 14.29,73.88 | 14.24,84.81 14.29,84.85 U$2.VCC 14.29,84.69 14.13,84.53 14.13,84.14 | 14.13,84.14 14.13,84.13 | 14.44,73.73 14.45,73.74 14.13,74.06 14.13,84.14 | 14.44,73.73

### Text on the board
Top: ATARI XE - PBI Adapter | +5V
tPlace: 1K | for ABBUC FREEZER 2011 | A | K | (C) 08/2011 ABBUC/mega-hz
tStop: ATARI XE - PBI Adapter | +5V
